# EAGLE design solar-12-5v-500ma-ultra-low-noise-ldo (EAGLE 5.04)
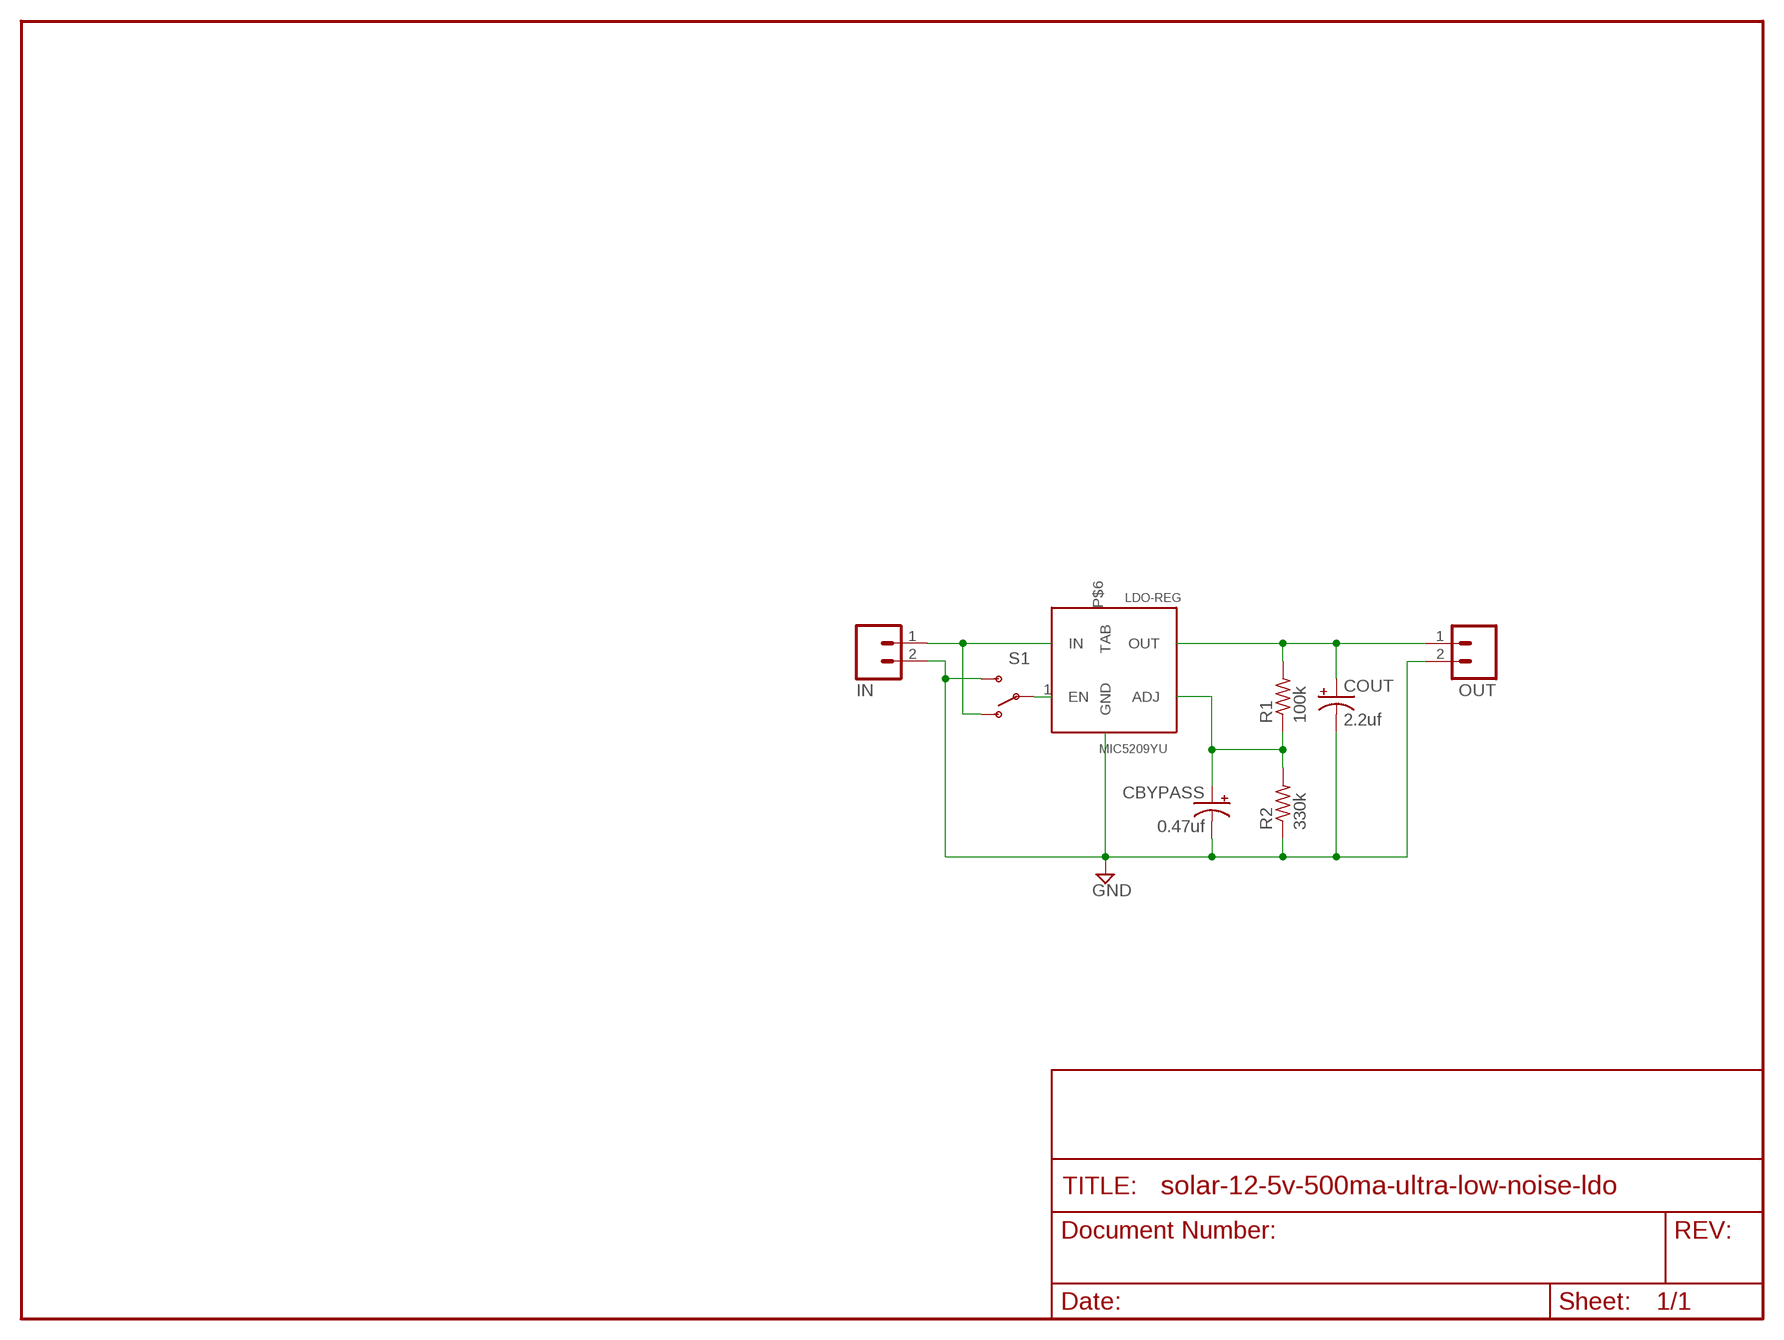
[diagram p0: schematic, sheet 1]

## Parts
CBYPASS  0.47uf  CPOL-USE5-5  [E5-5]
COUT  2.2uf  CPOL-USE5-5  [E5-5]
IN  M02POLAR  [MOLEX-1X2]
LDO-REG  MIC5209YU  [TO-263-5]
OUT  M02POLAR  [MOLEX-1X2]
R1  100k  R-US_0207/10  [0207/10]
R2  330k  R-US_0207/10  [0207/10]
S1  SWITCH-SPSTSMD2  [SWITCH-SPDT-SMD]

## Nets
GND: CBYPASS.- COUT.- IN.2 LDO-REG.P$3(GND) OUT.2 R2.1 S1.3(S)
N$1: COUT.+ LDO-REG.P$4(OUT) OUT.1 R1.2
N$2: IN.1 LDO-REG.P$2(IN) S1.1(O)
N$3: LDO-REG.1(EN) S1.2(P)
N$4: CBYPASS.+ LDO-REG.P$5(ADJ) R1.1 R2.2
Unconnected: LDO-REG.P$6(TAB)

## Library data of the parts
CBYPASS COUT = rcl:CPOL-US: POLARIZED CAPACITOR, American symbol
IN OUT = SparkFun:M02: Header 2
LDO-REG = trl:MIC5209YU
R1 R2 = resistor:R-US_: RESISTOR, American symbol
S1 = SparkFun:SWITCH-SPST: SPST Switch Simple slide switch. Spark Fun Electronics SKU : COM-00102

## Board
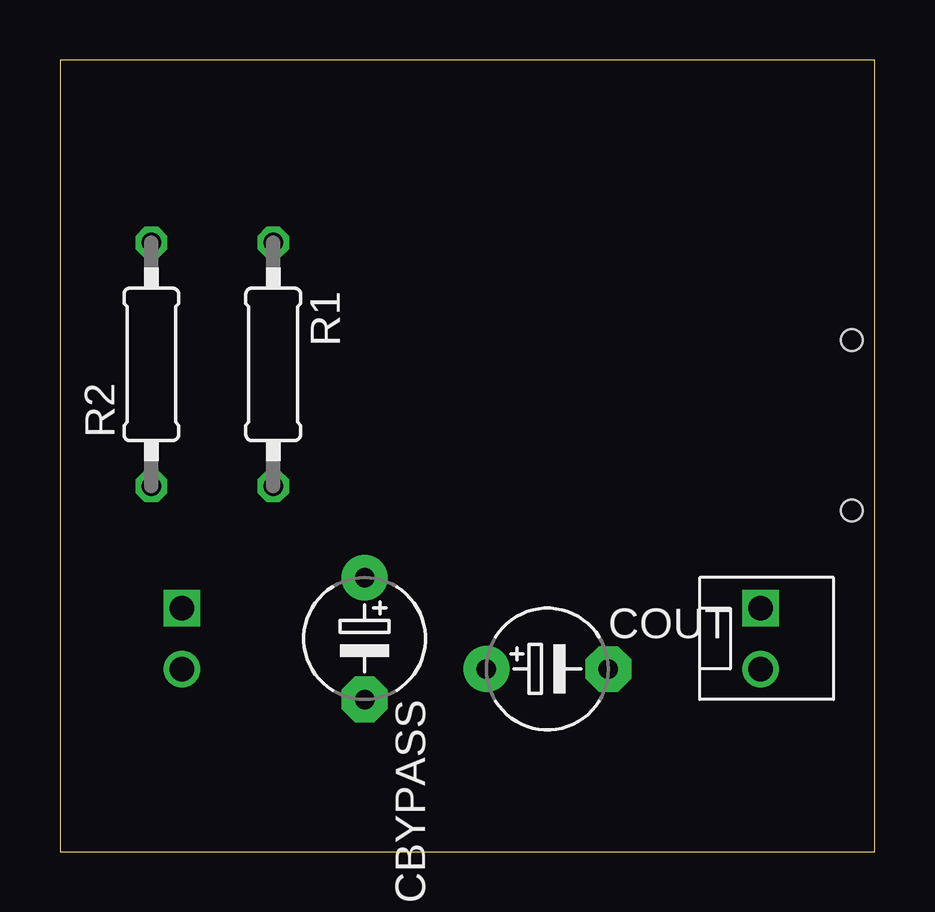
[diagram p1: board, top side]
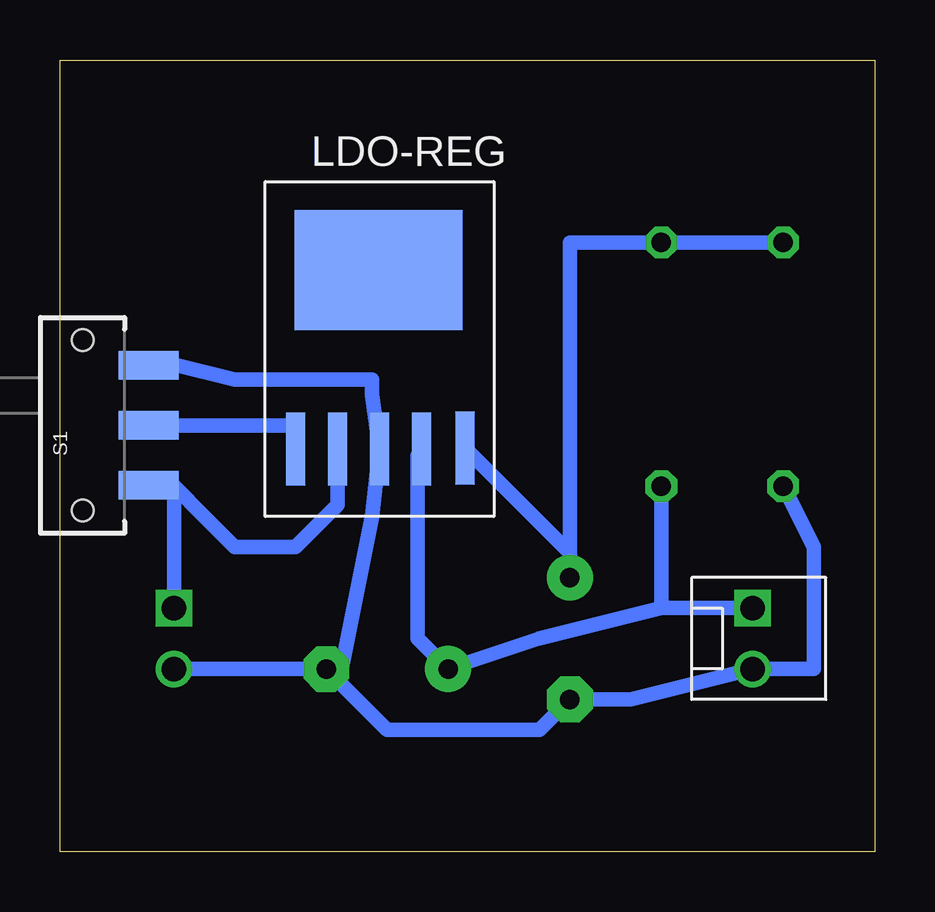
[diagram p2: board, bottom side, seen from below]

Size 33.96 x 33.01 mm. Coordinates in mm from the lower left corner, seen from the top.
Outline: 0,0 33.96,0 33.96,33.01 0,33.01 0,0
Copper layers (1*16): Top 0.035mm / dielectric 1.5mm / Bottom 0.035mm
Design rules "default *": minimum track width 24mil, minimum drill 24mil, track to track 12mil, track to pad 12mil, pad to pad 12mil, via to via 8mil, smd to smd 12mil, copper to edge 40mil, drill to drill 8mil, minimum pad ring 10mil, minimum via ring 8mil, stop-mask expansion 4mil, vias tented up to drill 0mil, thermal gap 10mil

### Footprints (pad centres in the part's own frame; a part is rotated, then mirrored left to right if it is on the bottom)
E5-5 = drill 0.813 pad 1.905 round: + -2.54,0 | drill 0.813 pad 1.905 octagon: - 2.54,0
MOLEX-1X2 = drill 1.016 square: 1 0,0 | drill 1.016 round: 2 2.54,0
TO-263-5 = smd 0.79 x 3.04: 1 0,1.55; P$2 1.75,1.55; P$3 3.5,1.55; P$4 5.25,1.55; P$5 7.05,1.6 | smd 7 x 5: P$6 3.45,9
0207/10 = drill 0.813 octagon: 1 -5.08,0; 2 5.08,0
SWITCH-SPDT-SMD = smd 1.2 x 2.5: 1 -2.5,-2.75; 2 0,-2.75; 3 2.5,-2.75 | hole 0.9: -3.55,0; 3.55,0

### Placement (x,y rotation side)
CBYPASS  12.7,8.89 270 top
COUT  20.32,7.62 0 top
IN  29.21,10.16 270 top
LDO-REG  24.13,15.24 0 bottom
OUT  5.08,10.16 270 bottom
R1  8.89,20.32 270 top
R2  3.81,20.32 90 top
S1  33.02,17.78 90 bottom

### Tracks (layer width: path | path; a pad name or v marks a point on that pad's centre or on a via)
GND
  Bottom 0.61: S1.3 29.21,20.32 26.67,19.68 20.95,19.68 20.95,19.05 LDO-REG.P$3 20.95,13.97 22.23,7.62 COUT.- | COUT.- IN.2 | R2.1 2.54,12.7 2.54,10.16 2.54,7.62 OUT.2 10.16,6.35 CBYPASS.- 13.97,5.08 20.32,5.08 COUT.-
N$1
  Bottom 0.61: 8.89,10.16 R1.2 | OUT.1 8.89,10.16 | LDO-REG.P$4 19.05,16.51 19.05,8.89 COUT.+ 13.97,8.89 8.89,10.16
N$2
  Bottom 0.61: IN.1 29.21,15.24 | 29.21,15.24 S1.1 | 29.21,15.24 27.94,13.97 26.67,12.7 24.13,12.7 22.38,14.45 LDO-REG.P$2
N$3
  Bottom 0.61: S1.2 29.21,17.78 24.13,17.78 LDO-REG.1
N$4
  Bottom 0.61: R2.2 R1.1 12.7,25.4 12.7,12.46 | 12.7,12.46 CBYPASS.+ 12.7,12.46 | 12.7,12.46 LDO-REG.P$5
